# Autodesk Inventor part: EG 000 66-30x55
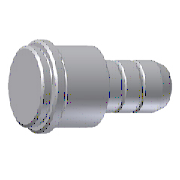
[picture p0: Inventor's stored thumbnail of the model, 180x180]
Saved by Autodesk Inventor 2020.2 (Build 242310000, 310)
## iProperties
Manager: www.cadconsulting.pl
Company: Fabian Stasiak CAD Consulting
IsCustomPart: 0
Created: 2014-02
Part Number: EG 000 66-30x55
Material: DIN 1.7131
Description: Leader Pins
Document SubType Name: Modeling
Designer: F.Stasiak
Standard Revision: 1
Manufacturer: DME
Language: pl-PL
Size Designation: 66-30x55
Categories: <MemberInstance><Categories><Category DisplayName="Forma wtryskowa" InternalName="349578f2-f4d4-4954-8c09-8e99297a61c0" Mnemonic="MOLD"><Category DisplayName="K
Mass: 4.19143 g
Surface Area: 17.8137 cm^2
Volume: 4.19143 cm^3
Density: 7.85 g/cm^3
Appearance: Stal
Catalog Web Link: www.expertbooks.pl
Author: F.Stasiak
Subject: Zbiór ćwiczeń. Autodesk Inventor 2020. Kurs Professional
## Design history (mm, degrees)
sketch "Sketch1"
  geometry: L1 (0, -42.393)-(0, 14.066) reference; L2 (0, 15)-(21, 15); L3 (21, 15)-(21, 7); L4 (20.5, 6)-(23.5, 6); L5 (23.5, 6)-(23.5, 0); L6 (23.5, 0)-(20.5, 0); L7 (21, -1)-(21, -58); L8 (21, -58)-(21, -58); L9 (21, -58)-(21, -60); L10 (21, -60)-(15, -60); L11 (15, -108)-(13.522, -113.518); L12 (11.59, -115)-(0, -115); L13 (15, -60)-(15, -108); L14 (20.5, 0)-(20.5, -1); L15 (20.5, -1)-(21, -1); L16 (20.5, 7)-(21, 7); L17 (20.5, 7)-(20.5, 6); L18 (0, 15)-(0, -115); A1 r 2 centre (11.59, -113) between (11.59, -115) and (13.522, -113.518); 1 further point
  constraints: 38 end point, 7 perpendicular, 6 parallel, 2 collinear, 2 point on circle, 2 point on line, 2 tangent, 2 vertical alignment, 1 centre point, 1 horizontal alignment
  dimensions: "d73" = 6 distance between parallel lines of L6 L4 (derived); "d74" = 9 distance between parallel lines of L2 L4 (derived); "d75" = 66 distance between parallel lines of L10 L4 (derived); "d76" = 2 distance between parallel lines of L10 L8; "d77" = 47 diameter of L5 L1 (derived); "d78" = 55 distance between parallel lines of L12 L10 (derived); "d79" = 42 diameter of L3 L1 (derived); "d89" = 7 distance from line of L12 L11.start (derived); "d92" = 30 diameter of L13 L1 (derived); "d94" = 42 diameter of L7 L1 (derived); "d97" = 2 radius of A1; "d110" = 0.5 distance between parallel lines of L7 L14; "d111" = 1 distance from line of L6.end L15; "d112" = 0.5 distance between parallel lines of L3 L17; "d113" = 1 distance between parallel lines of L4 L16; "d114" = 42 diameter of L9 L18 (derived); "d120" = 15 deg angle of L13 L11
revolve "Revolution1" sketch "Sketch1" stored, may be unused: angle "d100" = 90 deg
chamfer "Chamfer1" distance "d106" = 0.5; stored, may be unused: second distance "d107" = 2, angle "d108" = 45 deg
fillet "Fillet1" dims "d109" = 0.3
sketch "Sketch2"
  geometry: L1 (-11.59, -115)-(11.59, -115) reference; L2 (0, -40.8)-(0, 6.8) reference; C1 r 1.875 at (15.375, -76); C2 r 1.875 at (15.375, -92); 1 further point
  constraints: 2 centre point, 1 equal radius, 1 vertical alignment
  dimensions: "d121" = 3.75 diameter of C1 (derived); "d122" = 23 distance from line of L1 C2.centre (derived); "d123" = 39 distance from line of L1 C1.centre (derived); "d129" = 30.75 diameter of C1.centre L2 (derived)
revolve "Revolution2" sketch "Sketch2" stored, may be unused: angle "d126" = 90 deg
body "Solid1"
other parameters: "d3" = 47 [user parameter], "d2" = 42 [user parameter], "l2" = 9 [user parameter], "l1" = 6 [user parameter], "A_" = 66 [user parameter], "B" = 55 [user parameter], "d91" = 8, "d101" = 0, "d103" = 0, "ob" = 7 [user parameter], "d2_1" = 42 [user parameter], "d2_2" = 42 [user parameter], "B1" = 23 [user parameter], "G1" = 39 [user parameter], "d128" = 0, "L_" = 121 [user parameter]
